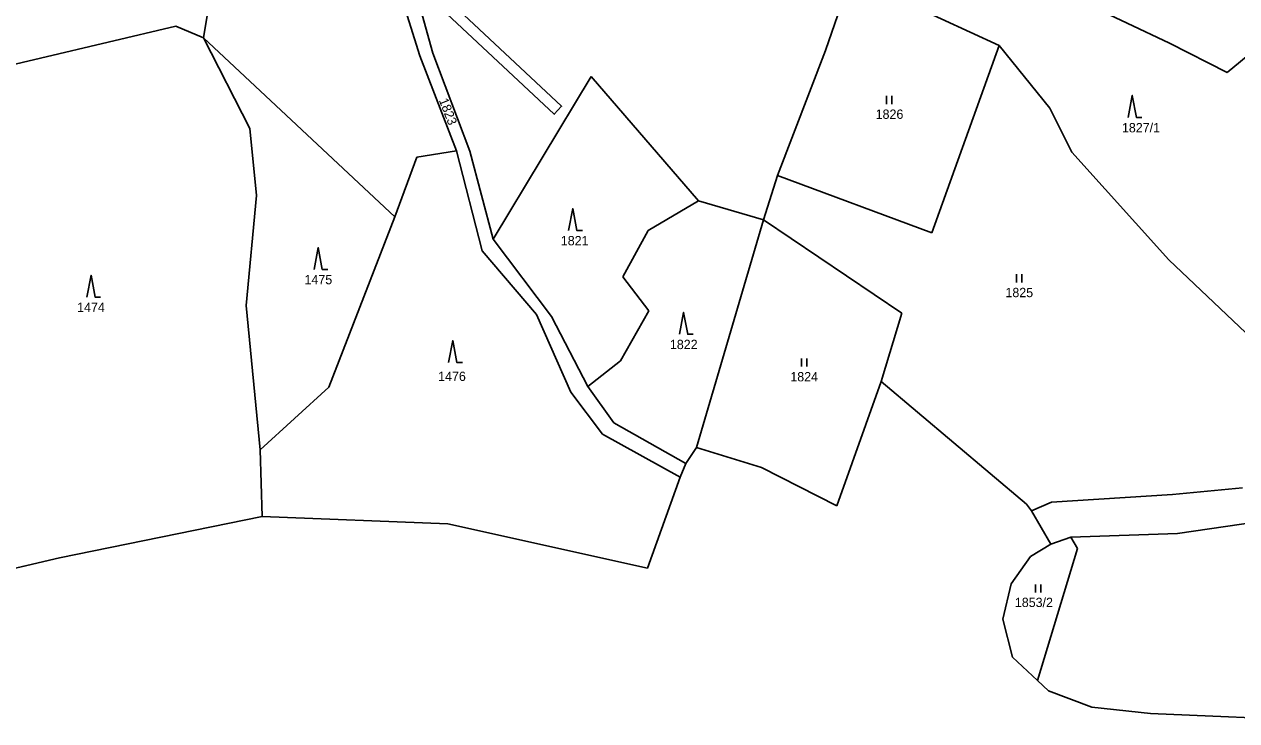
# Model space of a CAD drawing. Extents: x -670359 to -660124, y -978807 to -970072.
# Drawn here: x -669122.6 to -668901.2, y -978796.6 to -978669.5 of the extents above; entities that cross this region are included whole.
import ezdxf

# ---------------------------------------------------------------- set-up
doc = ezdxf.new("R2010")
doc.units = 0
for name, color, linetype in [('Hranice kat_území', 7, 'Continuous'), ('Hranice parcel', 7, 'Continuous'), ('Parcelní čísla', 7, 'Continuous'), ('Věcná břemena k části', 7, 'Continuous'), ('Značky kultur', 7, 'Continuous')]:
    doc.layers.add(name, color=color, linetype=linetype)

msp = doc.modelspace()

# ---------------------------------------------------------------- linework, layer by layer
at = {"layer": 'Hranice kat_území'}
for points in [[(-668974.22, -978757.37), (-668966.07, -978734.72)], [(-668966.07, -978734.72), (-668939.56, -978757.11)], [(-669001.78, -978749.69), (-668999.81, -978746.76)], [(-668999.81, -978746.76), (-668987.95, -978750.41)], [(-669002.79, -978752.15), (-669001.78, -978749.69)], [(-668987.95, -978750.41), (-668974.22, -978757.37)], [(-669008.76, -978768.77), (-669002.79, -978752.15)], [(-668939.56, -978757.11), (-668938.62, -978758.32)], [(-668938.62, -978758.32), (-668935.12, -978764.38)], [(-669116.14, -978766.86), (-669079.11, -978759.37)], [(-669079.11, -978759.37), (-669045.2, -978760.68)], [(-669045.2, -978760.68), (-669008.76, -978768.77)], [(-668935.12, -978764.38), (-668938.85, -978766.64)], [(-669129.14, -978769.92), (-669116.14, -978766.86)], [(-668938.85, -978766.64), (-668942.37, -978771.62)], [(-668942.37, -978771.62), (-668943.85, -978778.07)], [(-668943.85, -978778.07), (-668942.12, -978784.98)], [(-668942.12, -978784.98), (-668937.55, -978789.26)], [(-668935.51, -978791.17), (-668937.55, -978789.26)], [(-668935.51, -978791.17), (-668927.63, -978794.11)], [(-668927.63, -978794.11), (-668916.93, -978795.26)], [(-668916.93, -978795.26), (-668885.55, -978796.6)]]:
    msp.add_lwpolyline(points, dxfattribs=at)
at = {"layer": 'Hranice parcel'}
for points in [[(-669086.51, -978651.84), (-669089.85, -978672.04)], [(-668972.35, -978663.01), (-668976.23, -978674.31)], [(-668913.45, -978673.01), (-668936.64, -978661.96)], [(-669053.93, -978663.82), (-669050.36, -978675.32)], [(-669051.12, -978663.39), (-669047.95, -978674.8)], [(-668965.72, -978663.61), (-668944.52, -978673.42)], [(-669094.87, -978669.91), (-669132.02, -978678.62)], [(-669089.85, -978672.04), (-669094.87, -978669.91)], [(-669089.85, -978672.04), (-669081.38, -978688.53)], [(-669089.85, -978672.04), (-669054.9, -978704.7)], [(-668944.52, -978673.42), (-668956.87, -978707.6)], [(-668944.52, -978673.42), (-668935.27, -978684.87)], [(-668902.9, -978678.32), (-668913.45, -978673.01)], [(-669050.36, -978675.32), (-669043.62, -978692.64)], [(-669047.95, -978674.8), (-669041.22, -978692.68)], [(-668976.23, -978674.31), (-668985.03, -978697.11)], [(-668898.03, -978674.32), (-668902.9, -978678.32)], [(-669019.05, -978679.07), (-669036.93, -978708.75)], [(-668999.43, -978701.73), (-669019.05, -978679.07)], [(-668935.27, -978684.87), (-668931.25, -978692.86)], [(-669081.38, -978688.53), (-669080.14, -978700.78)], [(-669050.9, -978693.8), (-669054.9, -978704.7)], [(-669043.62, -978692.64), (-669050.9, -978693.8)], [(-669038.97, -978710.88), (-669043.62, -978692.64)], [(-669041.22, -978692.68), (-669036.93, -978708.75)], [(-668931.25, -978692.86), (-668913.58, -978712.53)], [(-668985.03, -978697.11), (-668987.57, -978705.22)], [(-668956.87, -978707.6), (-668985.03, -978697.11)], [(-669080.14, -978700.78), (-669082.04, -978720.84)], [(-669008.65, -978707.17), (-668999.43, -978701.73)], [(-668987.57, -978705.22), (-668999.43, -978701.73)], [(-669054.9, -978704.7), (-669066.94, -978735.74)], [(-668987.57, -978705.22), (-668999.81, -978746.76)], [(-668987.57, -978705.22), (-668962.33, -978722.23)], [(-669013.28, -978715.65), (-669008.65, -978707.17)], [(-669036.93, -978708.75), (-669026.29, -978722.86)], [(-669029.01, -978722.49), (-669038.97, -978710.88)], [(-668913.58, -978712.53), (-668899.48, -978725.81)], [(-669008.51, -978721.81), (-669013.28, -978715.65)], [(-669082.04, -978720.84), (-669079.46, -978747.2)], [(-669022.77, -978736.68), (-669029.01, -978722.49)], [(-669026.29, -978722.86), (-669019.63, -978735.62)], [(-669013.71, -978730.92), (-669008.51, -978721.81)], [(-668962.33, -978722.23), (-668966.07, -978734.72)], [(-669019.63, -978735.62), (-669013.71, -978730.92)], [(-669066.94, -978735.74), (-669079.46, -978747.2)], [(-669019.63, -978735.62), (-669014.94, -978742.26)], [(-669016.98, -978744.3), (-669022.77, -978736.68)], [(-669014.94, -978742.26), (-669001.78, -978749.69)], [(-669002.79, -978752.15), (-669016.98, -978744.3)], [(-669079.46, -978747.2), (-669079.11, -978759.37)], [(-668934.99, -978756.71), (-668912.88, -978755.34)], [(-668912.88, -978755.34), (-668900.13, -978754.12)], [(-668934.99, -978756.71), (-668938.62, -978758.32)], [(-668891.55, -978759.47), (-668911.96, -978762.42)], [(-668911.96, -978762.42), (-668931.46, -978763.13)], [(-668931.46, -978763.13), (-668935.12, -978764.38)], [(-668931.46, -978763.13), (-668930.24, -978765.16)], [(-668930.24, -978765.16), (-668937.55, -978789.26)]]:
    msp.add_lwpolyline(points, dxfattribs=at)
at = {"layer": 'Věcná břemena k části'}
msp.add_lwpolyline([(-669050.79, -978659.84), (-669024.44, -978684.5), (-669025.8, -978685.96), (-669051.02, -978662.36)], dxfattribs=at)
at = {"layer": 'Značky kultur'}
for p, q in [((-668965.14, -978682.6), (-668965.14, -978684.1)), ((-668964.14, -978684.1), (-668964.14, -978682.6)), ((-668941.4, -978715.13), (-668941.4, -978716.63)), ((-668940.4, -978716.63), (-668940.4, -978715.13)), ((-668980.64, -978730.49), (-668980.64, -978731.99)), ((-668979.64, -978731.99), (-668979.64, -978730.49)), ((-668937.94, -978771.72), (-668937.94, -978773.22)), ((-668936.94, -978773.22), (-668936.94, -978771.72))]:
    msp.add_line(p, q, dxfattribs=at)
for points in [[(-668920.99, -978686.53), (-668920.24, -978682.53), (-668919.49, -978686.53), (-668918.49, -978686.53)], [(-669023.16, -978707.17), (-669022.41, -978703.17), (-669021.66, -978707.17), (-669020.66, -978707.17)], [(-669069.64, -978714.27), (-669068.89, -978710.27), (-669068.14, -978714.27), (-669067.14, -978714.27)], [(-669111.12, -978719.32), (-669110.37, -978715.32), (-669109.62, -978719.32), (-669108.62, -978719.32)], [(-669002.92, -978726.1), (-669002.17, -978722.1), (-669001.42, -978726.1), (-669000.42, -978726.1)], [(-669045.07, -978731.26), (-669044.32, -978727.26), (-669043.57, -978731.26), (-669042.57, -978731.26)]]:
    msp.add_lwpolyline(points, dxfattribs=at)

# ---------------------------------------------------------------- texts
at = {"layer": 'Parcelní čísla'}
msp.add_text('1823', height=1.7, rotation=291.2092, dxfattribs=at).set_placement((-669046.88, -978683.4))
for s, p in [('1826', (-668967.1, -978686.8)), ('1827/1', (-668922.13, -978689.26)), ('1821', (-669024.59, -978709.87)), ('1475', (-669071.39, -978716.97)), ('1825', (-668943.4, -978719.33)), ('1474', (-669112.91, -978722.02)), ('1822', (-669004.67, -978728.8)), ('1476', (-669046.99, -978734.62)), ('1824', (-668982.68, -978734.69)), ('1853/2', (-668941.68, -978775.86))]:
    msp.add_text(s, height=1.7, dxfattribs=at).set_placement(p)

doc.saveas('drawing.dxf')
